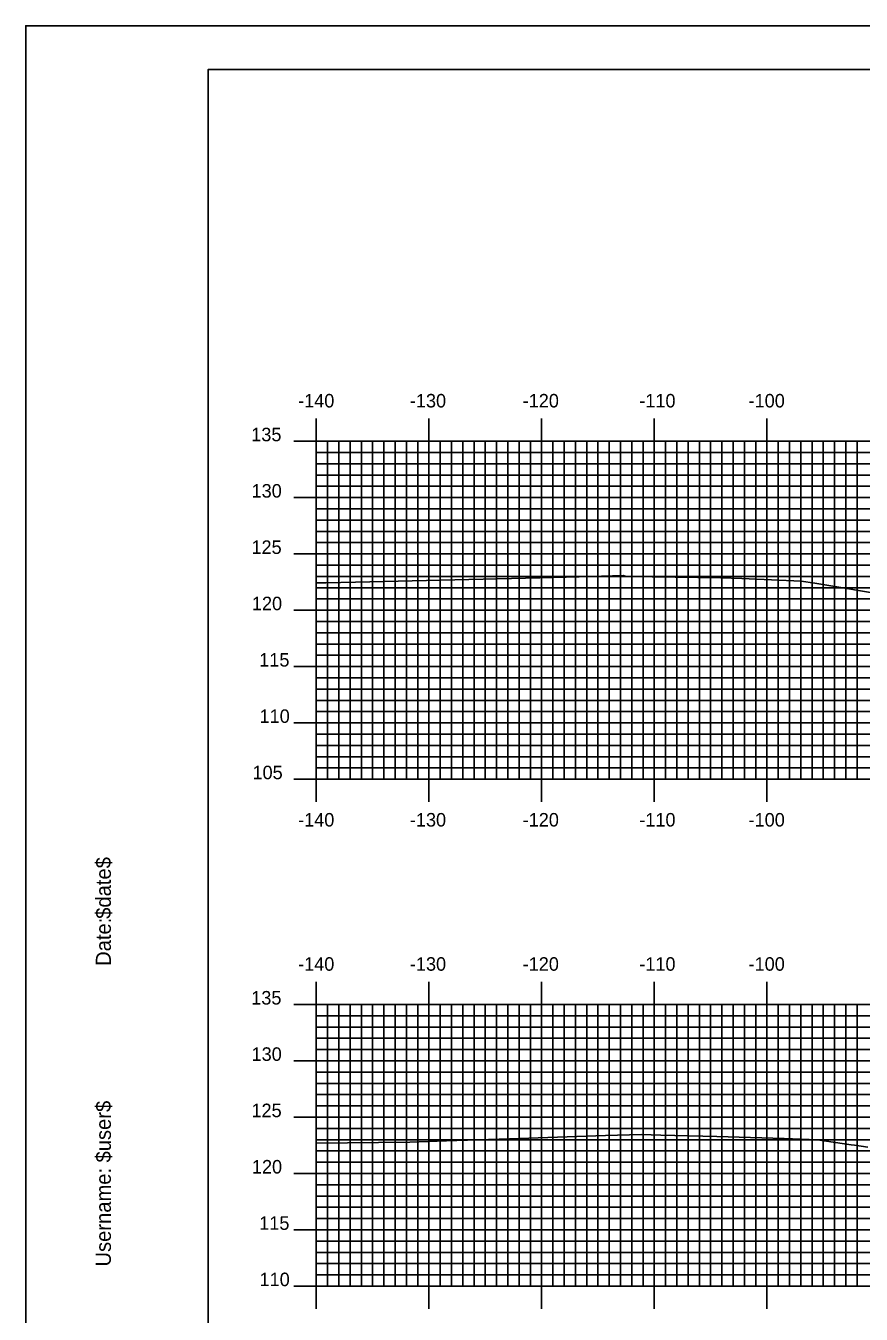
# Model space of a CAD drawing. Extents: x 843356 to 843699, y 363538 to 363758.
# Drawn here: x 843355.6 to 843429.8, y 363643.2 to 363757.6 of the extents above; entities that cross this region are included whole.
import ezdxf

# ---------------------------------------------------------------- set-up
doc = ezdxf.new("R2010")
doc.units = 0
for name, color, linetype in [('BORDER', 7, 'Continuous'), ('H_V ANNOTATION', 7, 'Continuous'), ('M_Roadway_Centerline', 7, 'Continuous'), ('MAJOR', 7, 'Continuous'), ('MINOR', 7, 'Continuous'), ('PLOT BOUNDARY', 7, 'Continuous'), ('S_Roadway_Centerline', 7, 'Continuous')]:
    doc.layers.add(name, color=color, linetype=linetype)

msp = doc.modelspace()

# ---------------------------------------------------------------- linework, layer by layer
at = {"layer": 'BORDER'}
msp.add_lwpolyline([(843371.82, 363543.72), (843691.82, 363543.72), (843691.82, 363753.72), (843371.82, 363753.72)], close=True, dxfattribs=at)
at = {"layer": 'MAJOR'}
for p, q in [((843381.42, 363722.73), (843381.42, 363720.72)), ((843391.42, 363722.73), (843391.42, 363720.72)), ((843401.42, 363722.73), (843401.42, 363720.72)), ((843411.42, 363722.73), (843411.42, 363720.72)), ((843421.42, 363722.73), (843421.42, 363720.72)), ((843379.42, 363720.72), (843381.42, 363720.72)), ((843381.42, 363720.72), (843661.42, 363720.72)), ((843381.42, 363690.72), (843381.42, 363720.72)), ((843381.42, 363690.72), (843381.42, 363720.72)), ((843381.42, 363720.72), (843661.42, 363720.72)), ((843391.42, 363690.72), (843391.42, 363720.72)), ((843401.42, 363690.72), (843401.42, 363720.72)), ((843411.42, 363690.72), (843411.42, 363720.72)), ((843421.42, 363690.72), (843421.42, 363720.72)), ((843379.42, 363715.72), (843381.42, 363715.72)), ((843381.42, 363715.72), (843661.42, 363715.72)), ((843379.42, 363710.72), (843381.42, 363710.72)), ((843381.42, 363710.72), (843661.42, 363710.72)), ((843379.42, 363705.72), (843381.42, 363705.72)), ((843381.42, 363705.72), (843661.42, 363705.72)), ((843379.42, 363700.72), (843381.42, 363700.72)), ((843381.42, 363700.72), (843661.42, 363700.72)), ((843379.42, 363695.72), (843381.42, 363695.72)), ((843381.42, 363695.72), (843661.42, 363695.72)), ((843379.42, 363690.72), (843381.42, 363690.72)), ((843381.42, 363690.72), (843661.42, 363690.72)), ((843381.42, 363690.72), (843661.42, 363690.72)), ((843381.42, 363688.72), (843381.42, 363690.72)), ((843391.42, 363688.72), (843391.42, 363690.72)), ((843401.42, 363688.72), (843401.42, 363690.72)), ((843411.42, 363688.72), (843411.42, 363690.72)), ((843421.42, 363688.72), (843421.42, 363690.72)), ((843381.42, 363672.73), (843381.42, 363670.72)), ((843391.42, 363672.73), (843391.42, 363670.72)), ((843401.42, 363672.73), (843401.42, 363670.72)), ((843411.42, 363672.73), (843411.42, 363670.72)), ((843421.42, 363672.73), (843421.42, 363670.72)), ((843379.42, 363670.72), (843381.42, 363670.72)), ((843381.42, 363670.72), (843661.42, 363670.72)), ((843381.42, 363645.72), (843381.42, 363670.72)), ((843381.42, 363645.72), (843381.42, 363670.72)), ((843381.42, 363670.72), (843661.42, 363670.72)), ((843391.42, 363645.72), (843391.42, 363670.72)), ((843401.42, 363645.72), (843401.42, 363670.72)), ((843411.42, 363645.72), (843411.42, 363670.72)), ((843421.42, 363645.72), (843421.42, 363670.72)), ((843379.42, 363665.72), (843381.42, 363665.72)), ((843381.42, 363665.72), (843661.42, 363665.72)), ((843379.42, 363660.72), (843381.42, 363660.72)), ((843381.42, 363660.72), (843661.42, 363660.72)), ((843379.42, 363655.72), (843381.42, 363655.72)), ((843381.42, 363655.72), (843661.42, 363655.72)), ((843379.42, 363650.72), (843381.42, 363650.72)), ((843381.42, 363650.72), (843661.42, 363650.72)), ((843379.42, 363645.72), (843381.42, 363645.72)), ((843381.42, 363645.72), (843661.42, 363645.72)), ((843381.42, 363645.72), (843661.42, 363645.72)), ((843381.42, 363643.72), (843381.42, 363645.72)), ((843391.42, 363643.72), (843391.42, 363645.72)), ((843401.42, 363643.72), (843401.42, 363645.72)), ((843411.42, 363643.72), (843411.42, 363645.72)), ((843421.42, 363643.72), (843421.42, 363645.72))]:
    msp.add_line(p, q, dxfattribs=at)
at = {"layer": 'MINOR'}
for p, q in [((843382.42, 363690.72), (843382.42, 363720.72)), ((843383.42, 363690.72), (843383.42, 363720.72)), ((843384.42, 363690.72), (843384.42, 363720.72)), ((843385.42, 363690.72), (843385.42, 363720.72)), ((843386.42, 363690.72), (843386.42, 363720.72)), ((843387.42, 363690.72), (843387.42, 363720.72)), ((843388.42, 363690.72), (843388.42, 363720.72)), ((843389.42, 363690.72), (843389.42, 363720.72)), ((843390.42, 363690.72), (843390.42, 363720.72)), ((843392.42, 363690.72), (843392.42, 363720.72)), ((843393.42, 363690.72), (843393.42, 363720.72)), ((843394.42, 363690.72), (843394.42, 363720.72)), ((843395.42, 363690.72), (843395.42, 363720.72)), ((843396.42, 363690.72), (843396.42, 363720.72)), ((843397.42, 363690.72), (843397.42, 363720.72)), ((843398.42, 363690.72), (843398.42, 363720.72)), ((843399.42, 363690.72), (843399.42, 363720.72)), ((843400.42, 363690.72), (843400.42, 363720.72)), ((843402.42, 363690.72), (843402.42, 363720.72)), ((843403.42, 363690.72), (843403.42, 363720.72)), ((843404.42, 363690.72), (843404.42, 363720.72)), ((843405.42, 363690.72), (843405.42, 363720.72)), ((843406.42, 363690.72), (843406.42, 363720.72)), ((843407.42, 363690.72), (843407.42, 363720.72)), ((843408.42, 363690.72), (843408.42, 363720.72)), ((843409.42, 363690.72), (843409.42, 363720.72)), ((843410.42, 363690.72), (843410.42, 363720.72)), ((843412.42, 363690.72), (843412.42, 363720.72)), ((843413.42, 363690.72), (843413.42, 363720.72)), ((843414.42, 363690.72), (843414.42, 363720.72)), ((843415.42, 363690.72), (843415.42, 363720.72)), ((843416.42, 363690.72), (843416.42, 363720.72)), ((843417.42, 363690.72), (843417.42, 363720.72)), ((843418.42, 363690.72), (843418.42, 363720.72)), ((843419.42, 363690.72), (843419.42, 363720.72)), ((843420.42, 363690.72), (843420.42, 363720.72)), ((843422.42, 363690.72), (843422.42, 363720.72)), ((843423.42, 363690.72), (843423.42, 363720.72)), ((843424.42, 363690.72), (843424.42, 363720.72)), ((843425.42, 363690.72), (843425.42, 363720.72)), ((843426.42, 363690.72), (843426.42, 363720.72)), ((843427.42, 363690.72), (843427.42, 363720.72)), ((843428.42, 363690.72), (843428.42, 363720.72)), ((843429.42, 363690.72), (843429.42, 363720.72)), ((843381.42, 363719.72), (843661.42, 363719.72)), ((843381.42, 363719.72), (843383.43, 363719.72)), ((843381.42, 363718.72), (843661.42, 363718.72)), ((843381.42, 363718.72), (843383.43, 363718.72)), ((843381.42, 363717.72), (843661.42, 363717.72)), ((843381.42, 363717.72), (843383.43, 363717.72)), ((843381.42, 363716.72), (843661.42, 363716.72)), ((843381.42, 363716.72), (843383.43, 363716.72)), ((843381.42, 363714.72), (843661.42, 363714.72)), ((843381.42, 363714.72), (843383.43, 363714.72)), ((843381.42, 363713.72), (843661.42, 363713.72)), ((843381.42, 363713.72), (843383.43, 363713.72)), ((843381.42, 363712.72), (843661.42, 363712.72)), ((843381.42, 363712.72), (843383.43, 363712.72)), ((843381.42, 363711.72), (843661.42, 363711.72)), ((843381.42, 363711.72), (843383.43, 363711.72)), ((843381.42, 363709.72), (843661.42, 363709.72)), ((843381.42, 363709.72), (843383.43, 363709.72)), ((843381.42, 363708.72), (843661.42, 363708.72)), ((843381.42, 363708.72), (843383.43, 363708.72)), ((843381.42, 363707.72), (843661.42, 363707.72)), ((843381.42, 363707.72), (843383.43, 363707.72)), ((843381.42, 363706.72), (843661.42, 363706.72)), ((843381.42, 363706.72), (843383.43, 363706.72)), ((843381.42, 363704.72), (843661.42, 363704.72)), ((843381.42, 363704.72), (843383.43, 363704.72)), ((843381.42, 363703.72), (843661.42, 363703.72)), ((843381.42, 363703.72), (843383.43, 363703.72)), ((843381.42, 363702.72), (843661.42, 363702.72)), ((843381.42, 363702.72), (843383.43, 363702.72)), ((843381.42, 363701.72), (843661.42, 363701.72)), ((843381.42, 363701.72), (843383.43, 363701.72)), ((843381.42, 363699.72), (843661.42, 363699.72)), ((843381.42, 363699.72), (843383.43, 363699.72)), ((843381.42, 363698.72), (843661.42, 363698.72)), ((843381.42, 363698.72), (843383.43, 363698.72)), ((843381.42, 363697.72), (843661.42, 363697.72)), ((843381.42, 363697.72), (843383.43, 363697.72)), ((843381.42, 363696.72), (843661.42, 363696.72)), ((843381.42, 363696.72), (843383.43, 363696.72)), ((843381.42, 363694.72), (843661.42, 363694.72)), ((843381.42, 363694.72), (843383.43, 363694.72)), ((843381.42, 363693.72), (843661.42, 363693.72)), ((843381.42, 363693.72), (843383.43, 363693.72)), ((843381.42, 363692.72), (843661.42, 363692.72)), ((843381.42, 363692.72), (843383.43, 363692.72)), ((843381.42, 363691.72), (843661.42, 363691.72)), ((843381.42, 363691.72), (843383.43, 363691.72)), ((843382.42, 363645.72), (843382.42, 363670.72)), ((843383.42, 363645.72), (843383.42, 363670.72)), ((843384.42, 363645.72), (843384.42, 363670.72)), ((843385.42, 363645.72), (843385.42, 363670.72)), ((843386.42, 363645.72), (843386.42, 363670.72)), ((843387.42, 363645.72), (843387.42, 363670.72)), ((843388.42, 363645.72), (843388.42, 363670.72)), ((843389.42, 363645.72), (843389.42, 363670.72)), ((843390.42, 363645.72), (843390.42, 363670.72)), ((843392.42, 363645.72), (843392.42, 363670.72)), ((843393.42, 363645.72), (843393.42, 363670.72)), ((843394.42, 363645.72), (843394.42, 363670.72)), ((843395.42, 363645.72), (843395.42, 363670.72)), ((843396.42, 363645.72), (843396.42, 363670.72)), ((843397.42, 363645.72), (843397.42, 363670.72)), ((843398.42, 363645.72), (843398.42, 363670.72)), ((843399.42, 363645.72), (843399.42, 363670.72)), ((843400.42, 363645.72), (843400.42, 363670.72)), ((843402.42, 363645.72), (843402.42, 363670.72)), ((843403.42, 363645.72), (843403.42, 363670.72)), ((843404.42, 363645.72), (843404.42, 363670.72)), ((843405.42, 363645.72), (843405.42, 363670.72)), ((843406.42, 363645.72), (843406.42, 363670.72)), ((843407.42, 363645.72), (843407.42, 363670.72)), ((843408.42, 363645.72), (843408.42, 363670.72)), ((843409.42, 363645.72), (843409.42, 363670.72)), ((843410.42, 363645.72), (843410.42, 363670.72)), ((843412.42, 363645.72), (843412.42, 363670.72)), ((843413.42, 363645.72), (843413.42, 363670.72)), ((843414.42, 363645.72), (843414.42, 363670.72)), ((843415.42, 363645.72), (843415.42, 363670.72)), ((843416.42, 363645.72), (843416.42, 363670.72)), ((843417.42, 363645.72), (843417.42, 363670.72)), ((843418.42, 363645.72), (843418.42, 363670.72)), ((843419.42, 363645.72), (843419.42, 363670.72)), ((843420.42, 363645.72), (843420.42, 363670.72)), ((843422.42, 363645.72), (843422.42, 363670.72)), ((843423.42, 363645.72), (843423.42, 363670.72)), ((843424.42, 363645.72), (843424.42, 363670.72)), ((843425.42, 363645.72), (843425.42, 363670.72)), ((843426.42, 363645.72), (843426.42, 363670.72)), ((843427.42, 363645.72), (843427.42, 363670.72)), ((843428.42, 363645.72), (843428.42, 363670.72)), ((843429.42, 363645.72), (843429.42, 363670.72)), ((843381.42, 363669.72), (843661.42, 363669.72)), ((843381.42, 363669.72), (843383.43, 363669.72)), ((843381.42, 363668.72), (843661.42, 363668.72)), ((843381.42, 363668.72), (843383.43, 363668.72)), ((843381.42, 363667.72), (843661.42, 363667.72)), ((843381.42, 363667.72), (843383.43, 363667.72)), ((843381.42, 363666.72), (843661.42, 363666.72)), ((843381.42, 363666.72), (843383.43, 363666.72)), ((843381.42, 363664.72), (843661.42, 363664.72)), ((843381.42, 363664.72), (843383.43, 363664.72)), ((843381.42, 363663.72), (843661.42, 363663.72)), ((843381.42, 363663.72), (843383.43, 363663.72)), ((843381.42, 363662.72), (843661.42, 363662.72)), ((843381.42, 363662.72), (843383.43, 363662.72)), ((843381.42, 363661.72), (843661.42, 363661.72)), ((843381.42, 363661.72), (843383.43, 363661.72)), ((843381.42, 363659.72), (843661.42, 363659.72)), ((843381.42, 363659.72), (843383.43, 363659.72)), ((843381.42, 363658.72), (843661.42, 363658.72)), ((843381.42, 363658.72), (843383.43, 363658.72)), ((843381.42, 363657.72), (843661.42, 363657.72)), ((843381.42, 363657.72), (843383.43, 363657.72)), ((843381.42, 363656.72), (843661.42, 363656.72)), ((843381.42, 363656.72), (843383.43, 363656.72)), ((843381.42, 363654.72), (843661.42, 363654.72)), ((843381.42, 363654.72), (843383.43, 363654.72)), ((843381.42, 363653.72), (843661.42, 363653.72)), ((843381.42, 363653.72), (843383.43, 363653.72)), ((843381.42, 363652.72), (843661.42, 363652.72)), ((843381.42, 363652.72), (843383.43, 363652.72)), ((843381.42, 363651.72), (843661.42, 363651.72)), ((843381.42, 363651.72), (843383.43, 363651.72)), ((843381.42, 363649.72), (843661.42, 363649.72)), ((843381.42, 363649.72), (843383.43, 363649.72)), ((843381.42, 363648.72), (843661.42, 363648.72)), ((843381.42, 363648.72), (843383.43, 363648.72)), ((843381.42, 363647.72), (843661.42, 363647.72)), ((843381.42, 363647.72), (843383.43, 363647.72)), ((843381.42, 363646.72), (843661.42, 363646.72)), ((843381.42, 363646.72), (843383.43, 363646.72))]:
    msp.add_line(p, q, dxfattribs=at)
at = {"layer": 'PLOT BOUNDARY'}
msp.add_lwpolyline([(843355.64, 363537.6), (843695.64, 363537.6), (843695.64, 363757.6), (843355.64, 363757.6)], close=True, dxfattribs=at)
at = {"layer": 'S_Roadway_Centerline'}
for points in [[(843381.42, 363708.15), (843381.63, 363708.15), (843382.26, 363708.14), (843384.91, 363708.21), (843401.27, 363708.6), (843404.74, 363708.68), (843408.7, 363708.79), (843408.83, 363708.75), (843411.22, 363708.69), (843417.33, 363708.59), (843419.2, 363708.54), (843424.45, 363708.31), (843425.68, 363708.12), (843439.63, 363705.78)], [(843381.42, 363658.41), (843389.72, 363658.51), (843392.99, 363658.62), (843398.58, 363658.79), (843407.08, 363659.08), (843410.28, 363659.17), (843412.01, 363659.12), (843416.97, 363659), (843422.94, 363658.84), (843425.9, 363658.72), (843428.9, 363658.27), (843429.19, 363658.24), (843430.36, 363658.06)]]:
    msp.add_lwpolyline(points, dxfattribs=at)

# ---------------------------------------------------------------- texts
at = {"layer": 'BORDER'}
for s, p in [('$date$', (843363.19, 363678.33)), ('Date:', (843363.19, 363674.15)), ('$user$', (843363.19, 363656.7)), ('Username:', (843363.19, 363647.46))]:
    msp.add_text(s, height=1.339, rotation=90, dxfattribs=at).set_placement(p)
at = {"layer": 'H_V ANNOTATION'}
for s, p in [('-140', (843379.81, 363723.72)), ('-130', (843389.73, 363723.72)), ('-120', (843399.74, 363723.72)), ('-110', (843410.09, 363723.72)), ('-100', (843419.79, 363723.72)), ('135', (843375.65, 363720.72)), ('130', (843375.68, 363715.72)), ('125', (843375.67, 363710.72)), ('120', (843375.71, 363705.72)), ('115', (843376.36, 363700.72)), ('110', (843376.39, 363695.72)), ('105', (843375.76, 363690.72)), ('-140', (843379.81, 363686.52)), ('-130', (843389.73, 363686.52)), ('-120', (843399.74, 363686.52)), ('-110', (843410.09, 363686.52)), ('-100', (843419.79, 363686.52)), ('-140', (843379.81, 363673.72)), ('-130', (843389.73, 363673.72)), ('-120', (843399.74, 363673.72)), ('-110', (843410.09, 363673.72)), ('-100', (843419.79, 363673.72)), ('135', (843375.65, 363670.72)), ('130', (843375.68, 363665.72)), ('125', (843375.67, 363660.72)), ('120', (843375.71, 363655.72)), ('115', (843376.36, 363650.72)), ('110', (843376.39, 363645.72))]:
    msp.add_text(s, height=1.2, dxfattribs=at).set_placement(p)
at = {"layer": 'M_Roadway_Centerline'}
for s, p in [('C', (843408.69, 363708.79)), ('L', (843408.7, 363708.78)), ('C', (843410.28, 363659.17)), ('L', (843410.28, 363659.16))]:
    msp.add_text(s, height=0.0146, dxfattribs=at).set_placement(p)
at = {"layer": 'MAJOR'}
for p in [(843381.42, 363690.72), (843381.42, 363645.72)]:
    msp.add_text('-', height=0.012, dxfattribs=at).set_placement(p)

doc.saveas('drawing.dxf')
